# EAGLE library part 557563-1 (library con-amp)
AMP connector
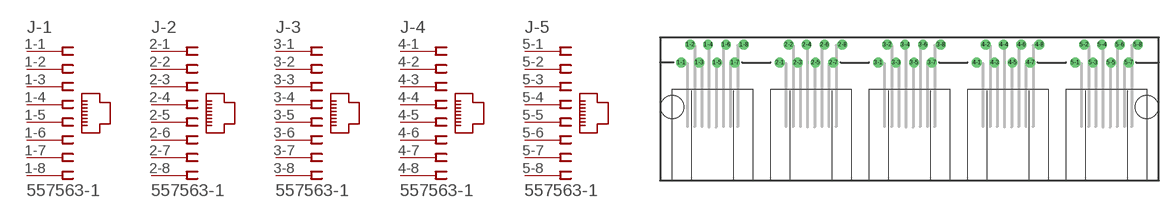
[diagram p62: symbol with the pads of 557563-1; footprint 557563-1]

Designator prefix J; gates -1=JACK8 -2=JACK8 -3=JACK8 -4=JACK8 -5=JACK8

## 557563-1 (MPN: 5557563-1; OC_FARNELL: 1821870; OC_NEWARK: 19R2786)  [557563-1]
1-1  -1:1  pas
1-2  -1:2  pas
1-3  -1:3  pas
1-4  -1:4  pas
1-5  -1:5  pas
1-6  -1:6  pas
1-7  -1:7  pas
1-8  -1:8  pas
2-1  -2:1  pas
2-2  -2:2  pas
2-3  -2:3  pas
2-4  -2:4  pas
2-5  -2:5  pas
2-6  -2:6  pas
2-7  -2:7  pas
2-8  -2:8  pas
3-1  -3:1  pas
3-2  -3:2  pas
3-3  -3:3  pas
3-4  -3:4  pas
3-5  -3:5  pas
3-6  -3:6  pas
3-7  -3:7  pas
3-8  -3:8  pas
4-1  -4:1  pas
4-2  -4:2  pas
4-3  -4:3  pas
4-4  -4:4  pas
4-5  -4:5  pas
4-6  -4:6  pas
4-7  -4:7  pas
4-8  -4:8  pas
5-1  -5:1  pas
5-2  -5:2  pas
5-3  -5:3  pas
5-4  -5:4  pas
5-5  -5:5  pas
5-6  -5:6  pas
5-7  -5:7  pas
5-8  -5:8  pas

## Footprint 557563-1 (pad centres in mm)
Modular Jack
drill 0.889 round: 1-1 -32.385,6.35; 1-2 -31.115,8.89; 1-3 -29.845,6.35; 1-4 -28.575,8.89; 1-5 -27.305,6.35; 1-6 -26.035,8.89; 1-7 -24.765,6.35; 1-8 -23.495,8.89; 2-1 -18.415,6.35; 2-2 -17.145,8.89; 2-3 -15.875,6.35; 2-4 -14.605,8.89; 2-5 -13.335,6.35; 2-6 -12.065,8.89; 2-7 -10.795,6.35; 2-8 -9.525,8.89; 3-1 -4.445,6.35; 3-2 -3.175,8.89; 3-3 -1.905,6.35; 3-4 -0.635,8.89; 3-5 0.635,6.35; 3-6 1.905,8.89; 3-7 3.175,6.35; 3-8 4.445,8.89; 4-1 9.525,6.35; 4-2 10.795,8.89; 4-3 12.065,6.35; 4-4 13.335,8.89; 4-5 14.605,6.35; 4-6 15.875,8.89; 4-7 17.145,6.35; 4-8 18.415,8.89; 5-1 23.495,6.35; 5-2 24.765,8.89; 5-3 26.035,6.35; 5-4 27.305,8.89; 5-5 28.575,6.35; 5-6 29.845,8.89; 5-7 31.115,6.35; 5-8 32.385,8.89
hole 3.251 at -33.655,0
hole 3.251 at 33.655,0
